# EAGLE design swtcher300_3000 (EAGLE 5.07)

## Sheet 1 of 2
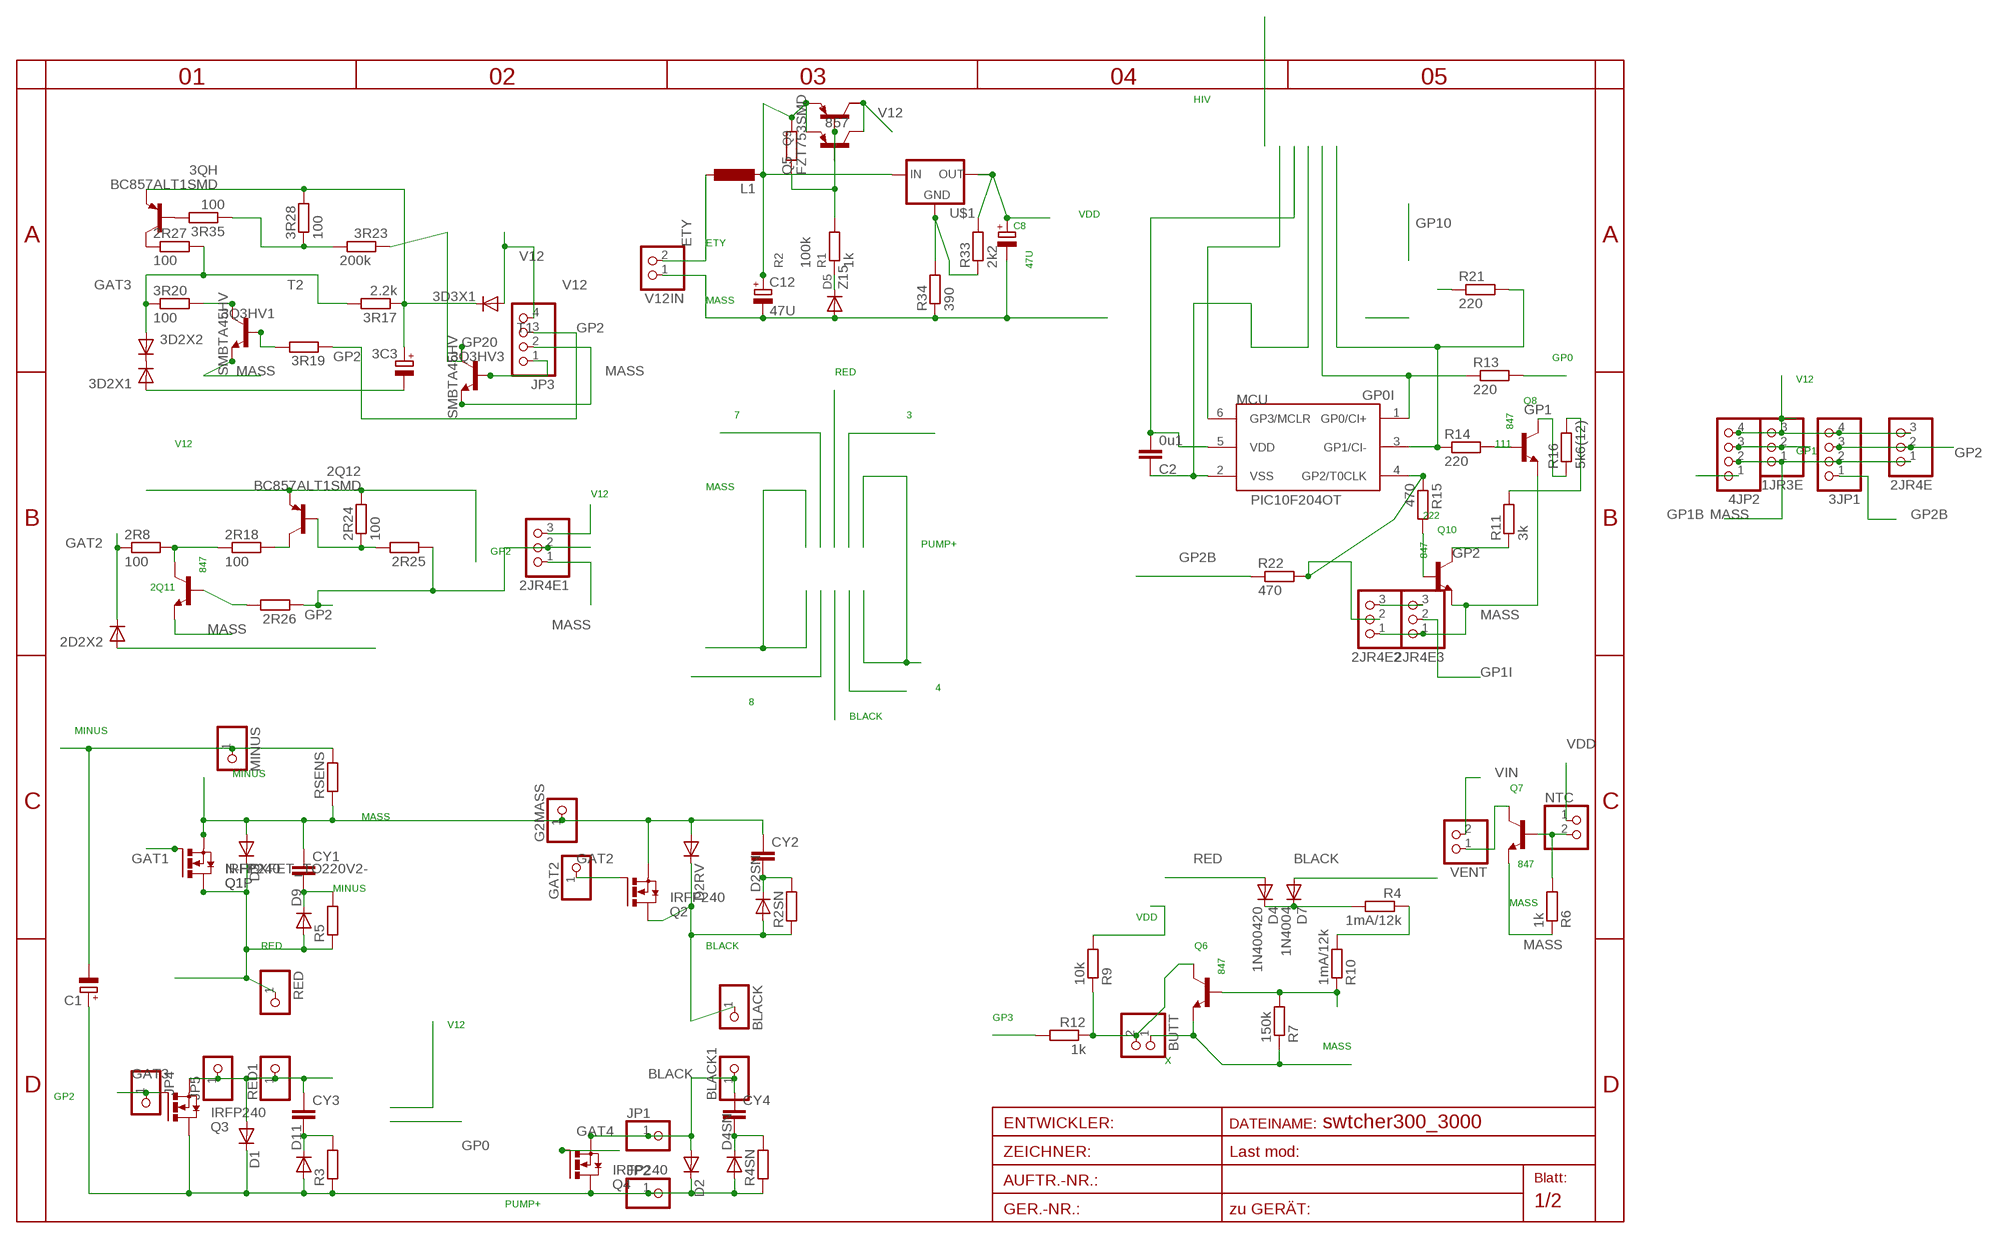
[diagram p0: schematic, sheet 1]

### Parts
1JR3E  PINHD-1X3  [1X03]
2D2X2  DIODE-MINIMELF  [MINIMELF]
2JR4E  PINHD-1X3  [1X03]
2JR4E1  PINHD-1X3  [1X03]
2JR4E2  PINHD-1X3  [1X03]
2JR4E3  PINHD-1X3  [1X03]
2Q11  847  BC847ALT1SMD  [SOT23]
2Q12  BC857ALT1SMD  [SOT23-BEC]
2R8  100  R-EU_R0805  [R0805]
2R18  100  R-EU_R0805  [R0805]
2R24  100  R-EU_R0805  [R0805]
2R25  R-EU_R0805  [R0805]
2R26  R-EU_R1206  [R1206]
2R27  100  R-EU_0207/10  [0207/10]
3C3  CPOL-EUD  [PANASONIC_D]
3D2X1  DIODE-MINIMELF  [MINIMELF]
3D2X2  DIODE-MINIMELF  [MINIMELF]
3D3X1  DIODE-SMA-DO214  [SMA-DO214AC]
3JP1  PINHD-1X4  [1X04]
3Q3HV1  SMBTA45HV  [SOT23HV]
3Q3HV3  SMBTA45HV  [SOT23HV]
3QH  BC857ALT1SMD  [SOT23-BEC]
3R17  2.2k  R-EU_R1206  [R1206]
3R19  R-EU_0204/3  [0204/3]
3R20  100  R-EU_0207/12  [0207/12]
3R23  200k  R-EU_0204/3  [0204/3]
3R28  100  R-EU_R0805  [R0805]
3R35  100  R-EU_R0805  [R0805]
4JP2  PINHD-1X4  [1X04]
BLACK  PINHD-1X14.5MM  [1X4MM5]
BLACK1  PINHD-1X12MM3  [1X2MM3]
BUTT  PINHD-1X2STR  [1X02]
C1  CPOL-EUE5-13  [E5-13]
C2  0u1  C-EUC0805  [C0805]
C8  47U  CPOL-EUD  [PANASONIC_D]
C12  47U  CPOL-EUSMCA  [SMC_A]
CY1  CXXC10B6  [XC10B6]
CY2  CXXC10B6  [XC10B6]
CY3  CXXC22B7  [XC22B7]
CY4  CXXC10B5  [XC10B5]
D1  DIODE-SMC  [SMC]
D2  DIODE-SMC  [SMC]
D2RV  DIODE-SMC  [SMC]
D2SN  DIODE-SOD61E  [SOD61E]
D3  DIODE-SMC  [SMC]
D4  1N400420  [DO41-20]
D4SN  DIODE-P1-10  [P1-10]
D5  Z15  DIODE-MINIMELF  [MINIMELF]
D7  1N4004  [D-7.5]
D9  DIODE-SOD61E  [SOD61E]
D11  DIODE-D-12.5  [D-12.5]
G2MASS  PINHD-1X11MM0  [1X1MM0]
GAT2  PINHD-1X11MM0  [1X1MM0]
JP1  PINHD-1X11MM0  [1X1MM0]
JP2  PINHD-1X11MM0  [1X1MM0]
JP3  PINHD-1X4  [1X04]
JP4  PINHD-1X11MM0  [1X1MM0]
JP5  PINHD-1X11MM0  [1X1MM0]
L1  L-EU0204/5  [0204/5]
MCU  PIC10F204OT  [SOT23-6]
MINUS  PINHD-1X14.5MM  [1X4MM5]
NTC  PINHD-1X2STR  [1X02]
Q1  IRFP240  [TO247BV]
Q1P  N-HEXFET_TO220V2-  [TO220BV2]
Q2  IRFP240  [TO247BV]
Q3  IRFP240  [TO247BV]
Q4  IRFP240  [TO247BV]
Q5  FZT753SMD  [SOT223]
Q6  847  BC847ALT1SMD  [SOT23]
Q7  847  BC847ALT1SMD  [SOT23]
Q8  847  BC847ALT1SMD  [SOT23]
Q9  857  BC857ALT1SMD  [SOT23-BEC]
Q10  847  BC847ALT1SMD  [SOT23]
R1  1k  R-EU_R0805  [R0805]
R2  100k  R-EU_R0805  [R0805]
R2SN  R-EU_0617/22  [0617/22]
R3  R-EU_0617/17  [0617/17]
R4  1mA/12k  R-EU_R1210  [R1210]
R4SN  R-EU_0207/10  [0207/10]
R5  R-EU_0617/22  [0617/22]
R6  1k  R-EU_R0805  [R0805]
R7  150k  R-EU_R0805  [R0805]
R9  10k  R-EU_R0805  [R0805]
R10  1mA/12k  R-EU_R1210  [R1210]
R11  3k  R-EU_R1206  [R1206]
R12  1k  R-EU_R0805  [R0805]
R13  220  R-EU_R0805  [R0805]
R14  220  R-EU_R0805  [R0805]
R15  470  R-EU_R0805  [R0805]
R16  5k6(12)  R-EU_R0805  [R0805]
R21  220  R-EU_R0805  [R0805]
R22  470  R-EU_R1206  [R1206]
R33  2k2  R-EU_R0805  [R0805]
R34  390  R-EU_R0805  [R0805]
RED  PINHD-1X14.5MM  [1X4MM5]
RED1  PINHD-1X12MM3  [1X2MM3]
RSENS  R-EU_CERAM35  [CERAM35]
T1  2N2222-NPN-TO92-EBC  [TO92-EBC]
T2  2N2222-NPN-TO92-EBC  [TO92-EBC]
U$1  AP1117  [SOT223]
V12IN  PINHD-1X2STR  [1X02]
VENT  PINHD-1X2STR  [1X02]

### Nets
111: Q8.1(B) R14.2
222: Q10.1(B) R15.2
BLACK: BLACK1.1 BLACK.1 CY4.1 D2.A D2RV.C D2SN.A D7.A JP1.1 Q2.D Q4.S R2SN.1
BTRAP+: 3C3.+ 3D3X1.K(C) 3QH.E 3R17.1 3R28.2
ETY: L1.1 V12IN.2
GAT1: Q1.G Q1P.G
GAT2: 2D2X2.C 2R8.1 GAT2.1 Q2.G
GAT3: 2R27.2 3D2X2.A 3R17.2 3R20.1 JP4.1 Q3.G
GAT4: Q4.G
GP0: R13.2
GP0I: MCU.1(GP0/CI+) R13.1 ; also sheet 2
GP1: 1JR3E.2 4JP2.3 Q8.3(C) R16.1
GP1B: 4JP2.1 R21.1
GP1I: 2JR4E3.2 MCU.3(GP1/CI-) R14.1 R21.2 ; also sheet 2
GP2: 2JR4E1.2 2JR4E.2 2R25.1 2R26.1 3JP1.3 3R19.1 JP3.3 Q10.3(C) R11.1
GP2B: 3JP1.1 3Q3HV3.1(B) JP3.1 R22.1 T1.B
GP2I: 2JR4E2.2 MCU.4(GP2/T0CLK) R15.1 R22.2 ; also sheet 2
GP3: MCU.6(GP3/MCLR) R12.2 ; also sheet 2
GP20: 3Q3HV3.3(C) 3R23.2 T1.C
HVC1: 3Q3HV1.3(C) 3R20.2 T2.C
MASS: 1JR3E.1 2D2X2.A 2JR4E1.1 2JR4E2.1 2JR4E3.1 2JR4E.1 2Q11.2(E) 3JP1.2 3Q3HV1.2(E) 3Q3HV3.2(E) 4JP2.2 BUTT.1 C2.1 C8.- C12.- CY1.1 CY2.1 D2RV.A D3.A D5.A G2MASS.1 JP3.2 MCU.2(VSS) Q1.S Q1P.S Q2.S Q6.2(E) Q7.2(E) Q8.2(E) Q10.2(E) R6.1 R7.1 R34.1 RSENS.1 T1.E T2.E V12IN.1 ; also sheet 2
MINUS: C1.- MINUS.1 RSENS.2
N$1: D4.C D7.C R4.2
N$2: Q5.1(B) Q9.B R1.2 R2.1
N$3: D5.C R1.1
N$4: 2Q11.3(C) 2R8.2 2R18.1
N$5: Q6.1(B) R7.2 R10.1
N$6: 2Q12.B 2R24.1 2R25.2
N$7: R4.1 R10.2
N$8: 2Q12.C 2R18.2
N$9: NTC.2 Q7.1(B) R6.2
N$10: Q7.3(C) VENT.1
N$12: 3Q3HV1.1(B) 3R19.2 T2.B
N$13: 2R27.1 3QH.C
N$17: 3QH.B 3R35.2
N$18: 3R23.1 3R28.1 3R35.1
N$21: 3D2X1.C 3D2X2.C
N$22: 2Q11.1(B) 2R26.2
N$30: R33.1 R34.2 U$1.1(GND)
PUMP+: C1.+ D1.C D2.C D4SN.A D11.A JP2.1 Q3.D Q4.D R3.1 R4SN.1 ; also sheet 2
RED: 3C3.- 3D2X1.A CY3.1 D1.A D3.C D4.A D9.A JP5.1 Q1.D Q1P.D Q3.S R5.1 RED1.1 RED.1
SNUB1: CY3.2 D11.C R3.2
SNUB2: CY4.2 D4SN.C R4SN.2
SNUB3: CY2.2 D2SN.C R2SN.2
SNUB4: CY1.2 D9.C R5.2
V12: 1JR3E.3 2JR4E1.3 2JR4E2.3 2JR4E3.3 2JR4E.3 2Q12.E 2R24.2 3D3X1.A 3JP1.4 4JP2.4 JP3.4 Q5.2(C) Q9.C R11.2 R16.2
VDD: C2.2 C8.+ MCU.5(VDD) NTC.1 R9.2 R33.2 U$1.2(OUT) U$1.4(TAB) ; also sheet 2
VIN: C12.+ L1.2 Q5.3(E) Q9.E R2.2 U$1.3(IN) VENT.2
X: BUTT.2 Q6.3(C) R9.1 R12.1
Unconnected: Q5.4(C/)

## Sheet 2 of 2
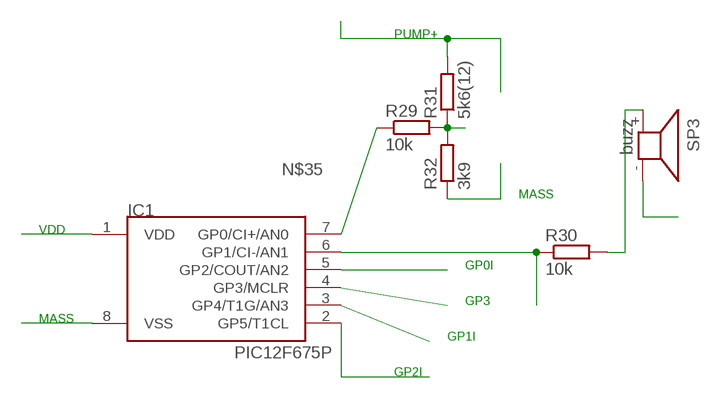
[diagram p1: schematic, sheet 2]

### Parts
IC1  PIC12F675P  [DIL8]
R29  10k  R-EU_R0805  [R0805]
R30  10k  R-EU_R0805  [R0805]
R31  5k6(12)  R-EU_0207/30  [0207/30]
R32  3k9  R-EU_R0805  [R0805]
SP3  buzz  KSS12017MM  [KSS1202]

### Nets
GP0I: IC1.5(GP2/COUT/AN2) ; also sheet 1
GP1I: IC1.3(GP4/T1G/AN3) ; also sheet 1
GP2I: IC1.2(GP5/T1CL) ; also sheet 1
GP3: IC1.4(GP3/MCLR) ; also sheet 1
MASS: IC1.8(VSS) R32.1 SP3.- ; also sheet 1
N$24: R30.2 SP3.+
N$31: IC1.6(GP1/CI-/AN1) R30.1
N$34: R29.2 R31.1 R32.2
N$35: IC1.7(GP0/CI+/AN0) R29.1
PUMP+: R31.2 ; also sheet 1
VDD: IC1.1(VDD) ; also sheet 1

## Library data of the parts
1JR3E 2JR4E 2JR4E1-2JR4E3 = pinhead:PINHD-1X3: PIN HEADER
2D2X2 3D2X1 3D2X2 3D3X1 D1 D2 D2RV D2SN D3 D4SN D5 D9 D11 = diode:DIODE-: DIODE
2Q11 Q6-Q8 Q10 = transistor-npn:BC847*: NPN Transistor
2Q12 3QH Q9 = transistor-pnp:BC857*: PNP Transistror
2R8 2R18 2R24-2R27 3R17 3R19 3R20 3R23 3R28 3R35 R2SN R4 R4SN R5-R7 R9 R10 R12 RSENS = rcl:R-EU_: RESISTOR, European symbol
3C3 C1 = rcl:CPOL-EU: POLARIZED CAPACITOR, European symbol
3JP1 4JP2 JP3 = pinhead:PINHD-1X4: PIN HEADER
3Q3HV1 3Q3HV3 = transistor-npn:SMBTA45
BLACK BLACK1 G2MASS GAT2 JP1 JP2 JP4 JP5 MINUS RED RED1 = pinhead:PINHD-1X1: PIN HEADER
BUTT NTC V12IN VENT = pinhead:PINHD-1X2: PIN HEADER
C2 = rcl:C-EU: CAPACITOR, European symbol
C8 C12 = rcl-2:CPOL-EU: POLARIZED CAPACITOR, European symbol
CY1-CY4 = rcl:CX: X CAPACITOR
D4 D7 = diode:1N4004: DIODE
IC1 = microchip-5:PIC12F6*: uPC nW 1k Program Flash memory 2x Timer Comparator 10b A/D converter/ 4xIN
L1 = rcl:L-EU: INDUCTOR, European symbol
MCU = microchip-3:PIC10F2*: uPC nW 0,25/0,5k Program Flash memory Comparator
Q1-Q4 = transistor-power:IRFP240: HEXFET Power MosFet Source: http://www.irf.com/
Q1P = transistor-power:N-HEXFET_?-*: HEXFET® Power MOSFET
Q5 = transistor-pnp:FZT753SMD: PNP Transistor
R1-R3 R11 R13-R16 R21 R22 R29-R34 = rcl-2:R-EU_: RESISTOR, European symbol
SP3 = buzzer:KSS1201: SPEAKER
T1 T2 = transistor-neu-to92:*-NPN-: NPN Transistror
U$1 = v-reg:AP1117

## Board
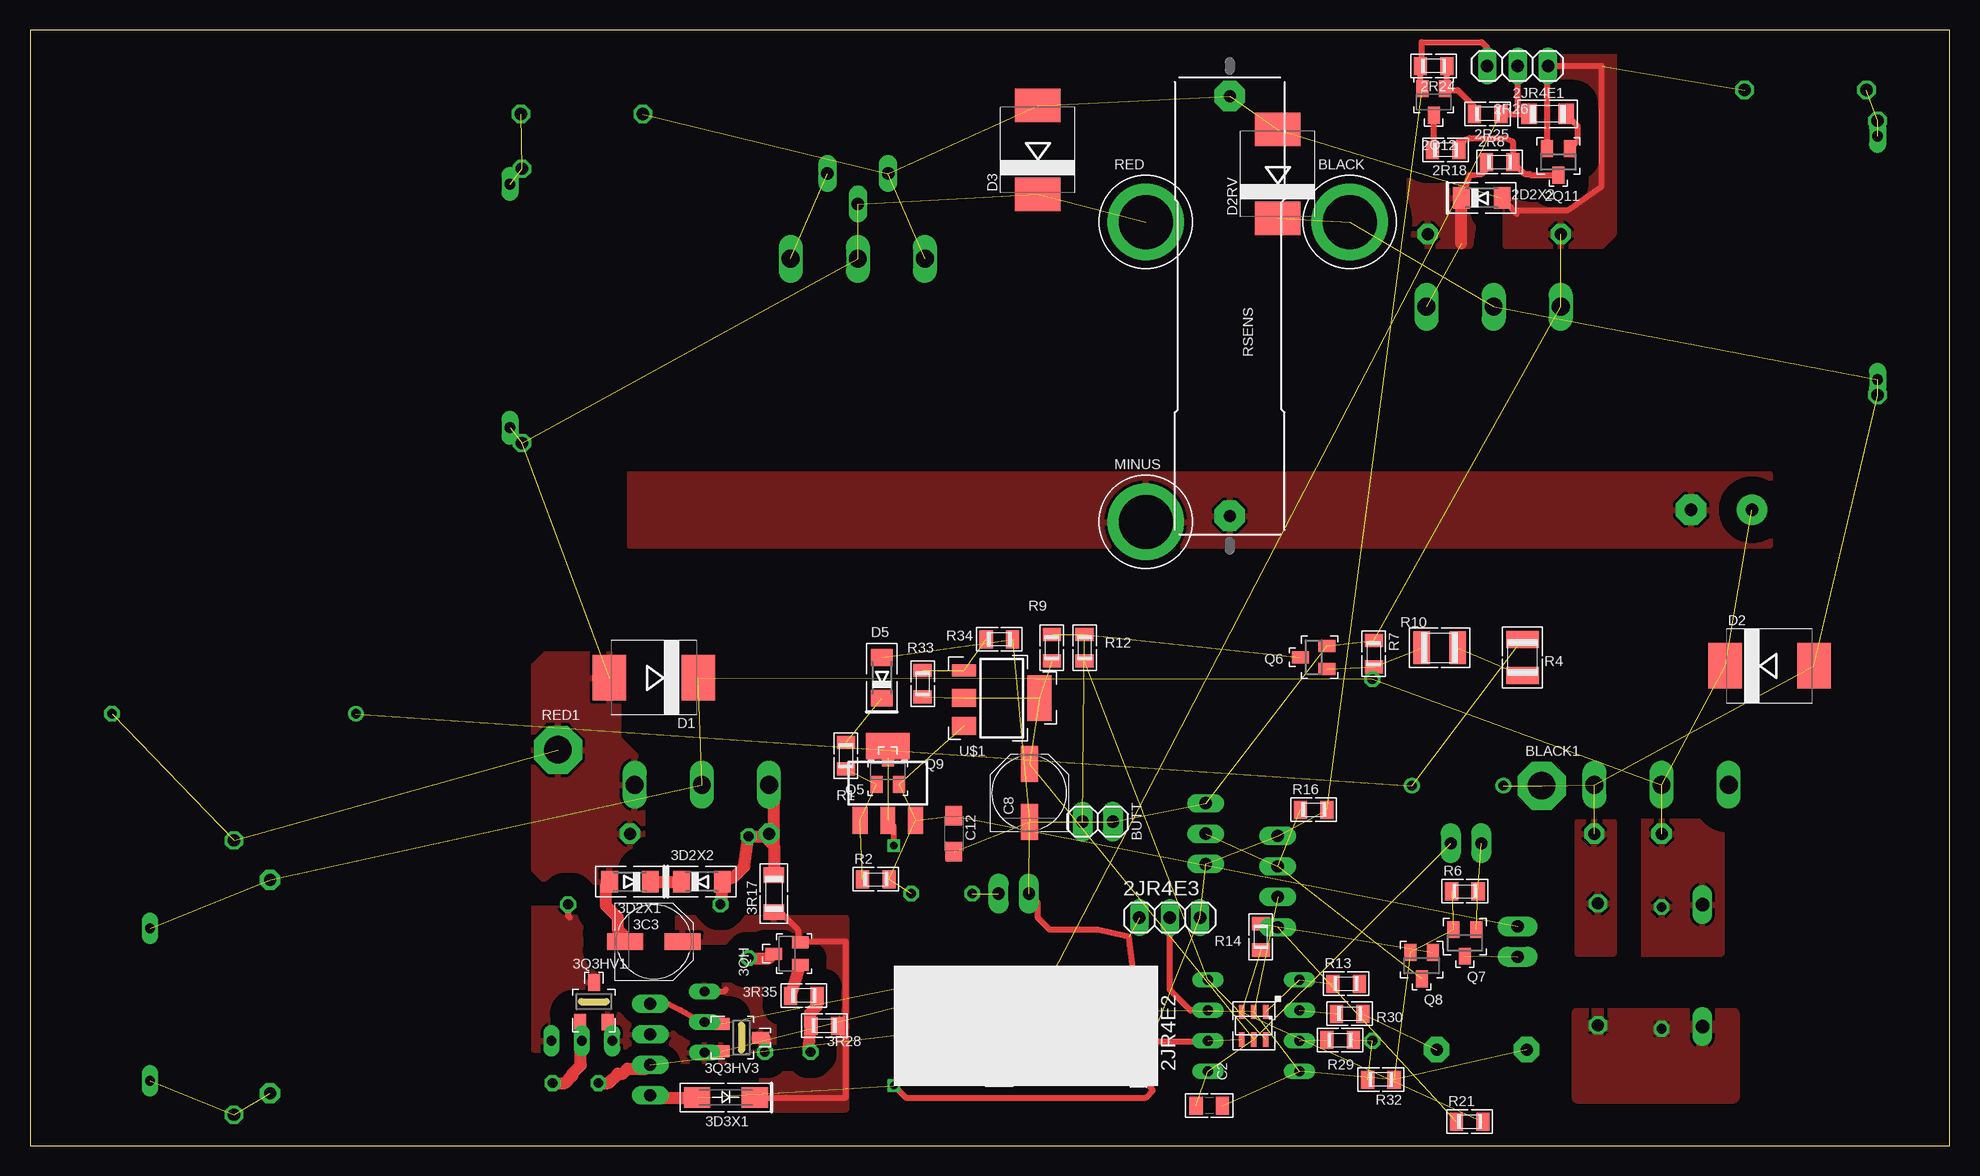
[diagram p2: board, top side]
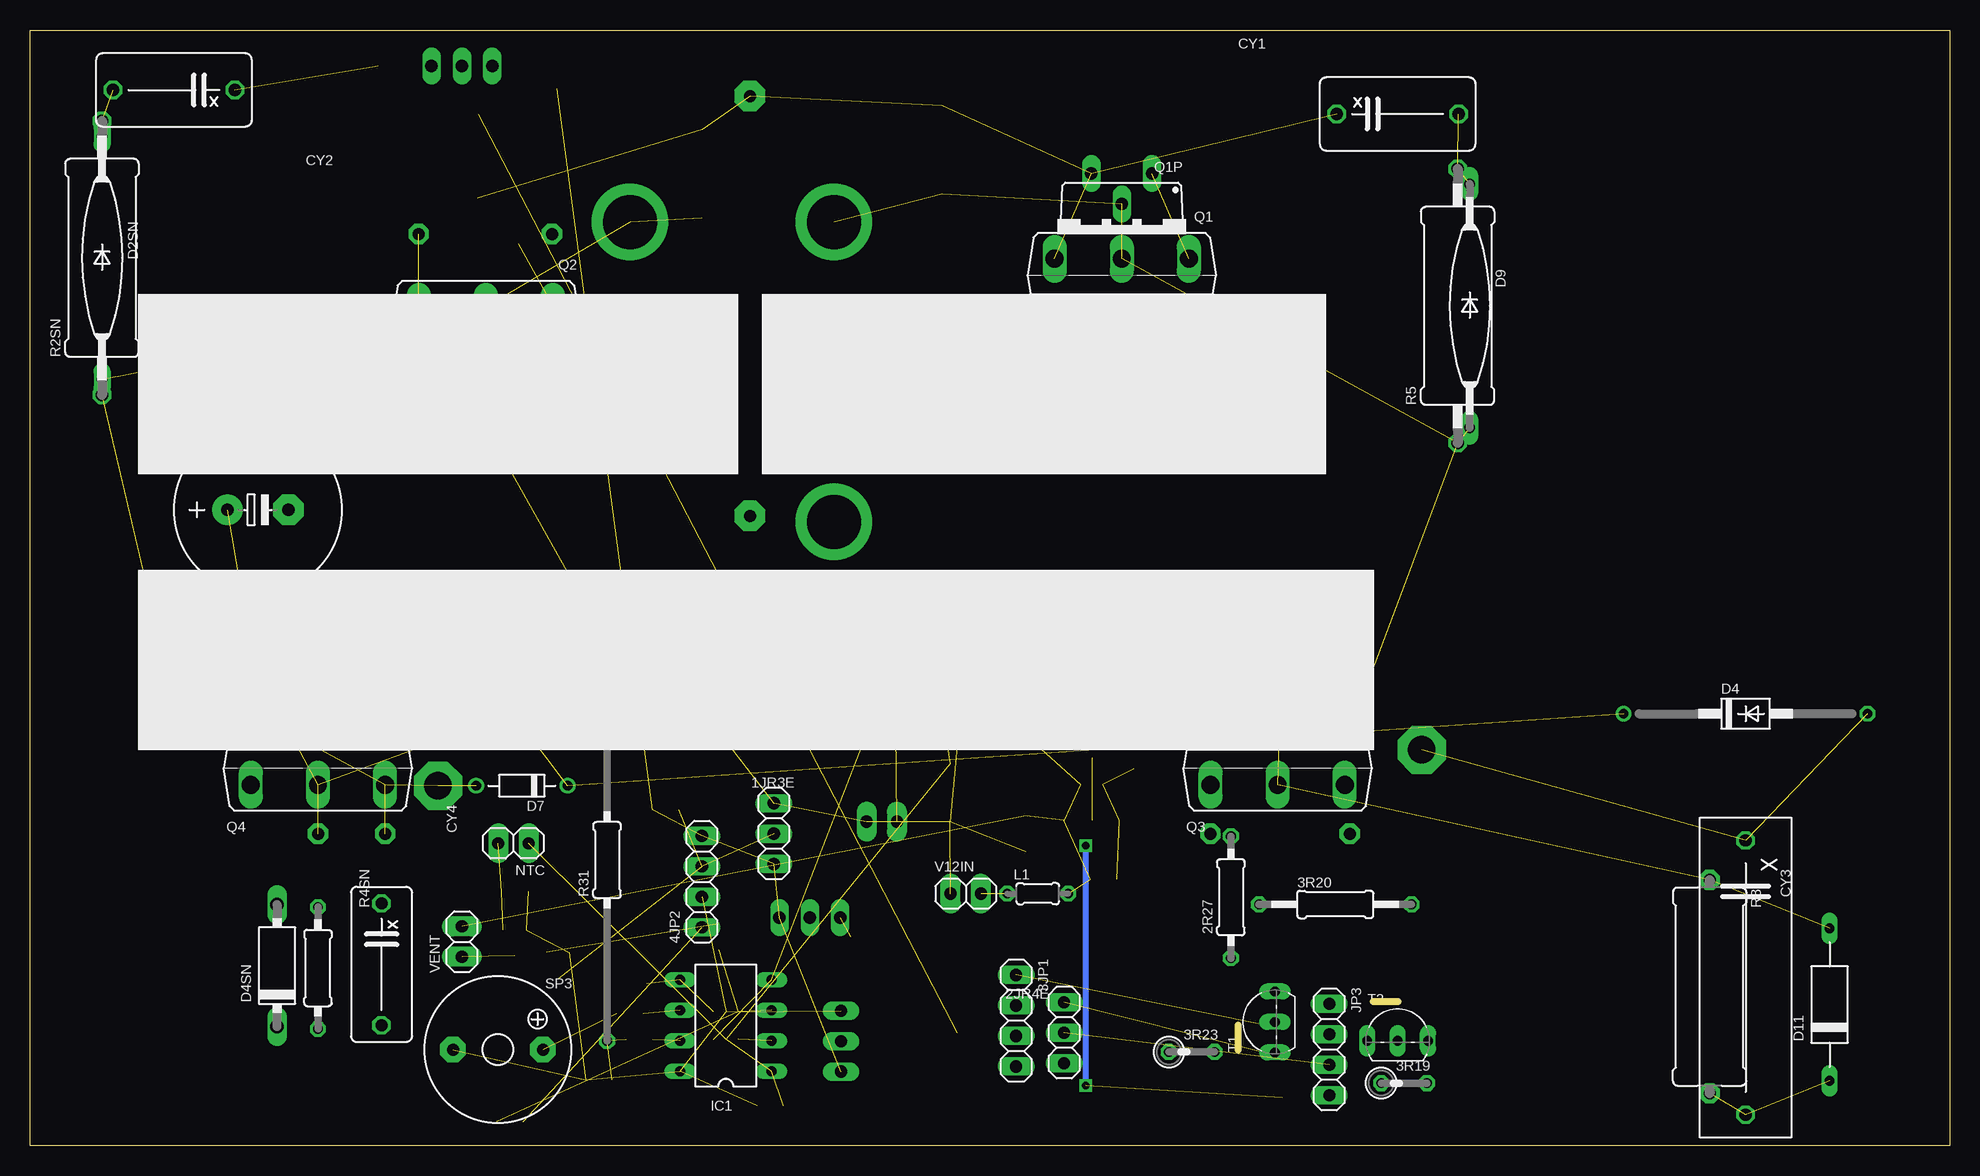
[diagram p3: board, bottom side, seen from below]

Size 160 x 93 mm. Coordinates in mm from the lower left corner, seen from the top.
Outline: 0,0 160,0 160,93 0,93 0,0
Copper layers (1*16): Top 0.035mm / dielectric 1.5mm / Bottom 0.035mm
Design rules "default *": minimum track width 10mil, minimum drill 20mil, track to track 8mil, track to pad 8mil, pad to pad 8mil, via to via 8mil, smd to smd 8mil, copper to edge 40mil, drill to drill 8mil, minimum pad ring 10mil, minimum via ring 8mil, stop-mask expansion 4mil, vias tented up to drill 0mil, thermal gap 10mil

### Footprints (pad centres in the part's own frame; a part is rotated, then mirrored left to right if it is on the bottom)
1X03 = drill 1.016 long: 1 -2.54,0; 2 0,0; 3 2.54,0
MINIMELF = smd 1.4 x 1.8: A 1.7,0; C -1.7,0
SOT23 = smd 1 x 1.4: 1 -0.95,-1.1; 2 0.95,-1.1; 3 0,1.1
SOT23-BEC = smd 1 x 1.4: B -0.95,-1.1; C 0,1.1; E 0.95,-1.1
R0805 = smd 1.1 x 1.5: 1 -1.1,0; 2 1.1,0
R1206 = smd 1.3 x 1.7: 1 -1.55,0; 2 1.55,0
0207/10 = drill 0.813 octagon: 1 -5.08,0; 2 5.08,0
PANASONIC_D = smd 3 x 1.4: + 2.4,0; - -2.4,0
SMA-DO214AC = smd 2.2 x 1.7: A 2.4,0; K -2.4,0
1X04 = drill 1.016 long: 1 -3.81,0; 2 -1.27,0; 3 1.27,0; 4 3.81,0
SOT23HV = smd 1 x 1.4: 1 -1.15,-1.7; 2 1.15,-1.7; 3 0,1.6
0204/3 = drill 0.813 octagon: 1 -1.27,0; 2 2.54,0
0207/12 = drill 0.813 octagon: 1 -6.35,0; 2 6.35,0
1X4MM5 = drill 4.5 pad 6.35 round: 1 0,0
1X2MM3 = drill 2.3 pad 4 octagon: 1 0,0
1X02 = drill 1.016 pad 1.676 long: 1 -1.27,0; 2 1.27,0
E5-13 = drill 1.016 pad 2.54 round: + -2.54,0 | drill 1.016 pad 2.54 octagon: - 2.54,0
C0805 = smd 1.1 x 1.5: 1 -1.1,0; 2 1.1,0
SMC_A = smd 1.6 x 1.4: + -1.5,0; - 1.5,0
XC10B6 = drill 1.016 octagon: 1 -5.08,0; 2 5.08,0
XC22B7 = drill 1.016 octagon: 1 -11.43,0; 2 11.43,0
XC10B5 = drill 1.016 octagon: 1 -5.08,0; 2 5.08,0
SMC = smd 2.8 x 3.8: A 3.7,0; C -3.7,0
SOD61E = drill 0.914 long: A 10.16,0; C -10.16,0
DO41-20 = drill 0.8 octagon: A 10.16,0 | drill 0.8 round: C -10.16,0
P1-10 = drill 1.118 long: A 5.08,0; C -5.08,0
D-7.5 = drill 0.8 round: A 3.81,0; C -3.81,0
D-12.5 = drill 0.813 long: A 6.35,0; C -6.35,0
1X1MM0 = drill 1 pad 1.676 octagon: 1 0,0
DIL8 = drill 0.8 long: 1 -3.81,-3.81; 2 -1.27,-3.81; 3 1.27,-3.81; 4 3.81,-3.81; 5 3.81,3.81; 6 1.27,3.81; 7 -1.27,3.81; 8 -3.81,3.81
0204/5 = drill 0.813 octagon: 1 -2.54,0; 2 2.54,0
SOT23-6 = smd 0.45 x 1.2: 1 -1.016,-1.15; 2 0,-1.15; 3 1.016,-1.15; 4 1.016,1.15; 5 0,1.15; 6 -1.016,1.15
TO247BV = drill 1.499 long: D 0,-2.921; G -5.588,-2.921; S 5.588,-2.921
TO220BV2 = drill 1.016 long: D 0,0; G -2.54,-2.54; S 2.54,-2.54
SOT223 = smd 1.219 x 2.235: 1 -2.311,-3.099; 2 0,-3.099; 3 2.311,-3.099 | smd 3.6 x 2.2: 4 0,3.099
0617/22 = drill 1.016 octagon: 1 -11.43,0; 2 11.43,0
0617/17 = drill 1 pad 1.676 octagon: 1 -8.89,0; 2 8.89,0
R1210 = smd 1.4 x 2.7: 1 -1.5,0; 2 1.5,0
0207/30 = drill 0.813 octagon: 1 -15.08,0; 2 15.08,0
CERAM35 = drill 1 pad 2.54 octagon: 1 -17.5,0; 2 17.5,0
KSS1202 = drill 1 pad 2.159 octagon: + 3.75,0; - -3.75,0
TO92-EBC = drill 0.813 long: B 0,-1.27; C 2.54,-1.27; E -2.54,-1.27
SOT223' = smd 1 x 2: 1 -2.3,-3.15 | smd 1.5 x 2: 2 0,-3.15; 3 2.3,-3.15 | smd 3.8 x 2: 4 0,3.15

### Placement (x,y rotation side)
1JR3E  98,26 270 bottom
2D2X2  121,79 0 top
2JR4E  73.8,9.4 270 bottom
2JR4E1  124,90 180 top
2JR4E2  92.4,8.7 270 top
2JR4E3  95,19 0 top
2Q11  127.4,82 180 top
2Q12  117,87 180 top
2R8  122.5,82 0 top
2R18  118,83 180 top
2R24  117,90 180 top
2R25  121.5,86 180 top
2R26  126.5,86 0 top
2R27  59.9,20.7 90 bottom
3C3  52,17 0 top
3D2X1  50,22 180 top
3D2X2  56,22 0 top
3D3X1  58,4 180 top
3JP1  77.8,10.4 270 bottom
3Q3HV1  47,12 0 top
3Q3HV3  59.3,9 270 top
3QH  63.1,16 90 top
3R17  62,21 90 top
3R19  46.1,5.2 0 bottom
3R20  51.2,20.1 0 bottom
3R23  63.8,7.8 0 bottom
3R28  66.2,10 0 top
3R35  64.5,12.5 180 top
4JP2  104,22 90 bottom
BLACK  110,77 0 top
BLACK1  126,30 0 top
BUTT  89,27 180 top
C1  141,53 0 bottom
C2  98.3,3.32 180 top
C8  83.3,29.4 90 top
C12  77,26 270 top
CY1  46,86 0 bottom
CY2  148,88 180 bottom
CY3  17,14 270 bottom
CY4  130.7,15.1 270 bottom
D1  52,39 180 top
D2  145,40 0 top
D2RV  104,81 90 top
D2SN  154,74 270 bottom
D3  84,83 90 top
D4  17,36 0 bottom
D4SN  139.4,15 90 bottom
D5  71,39 90 top
D7  119,30 180 bottom
D9  40,70 270 bottom
D11  10,11.75 90 bottom
G2MASS  127.6,76 0 top
GAT2  116.5,76 0 top
IC1  102,10 90 bottom
JP1  130.4,26 0 top
JP2  136,26 0 top
JP3  51.7,8 270 bottom
JP4  61.6,26 0 top
JP5  50,26 0 top
L1  76,21 0 bottom
MCU  102,10 180 top
MINUS  93,52 0 top
NTC  119.7,25.2 180 bottom
Q1  69,71 180 bottom
Q1P  69,78.5 180 bottom
Q2  122,67 180 bottom
Q3  56,33 0 bottom
Q4  136,33 0 bottom
Q5  71.5,30.2 0 top
Q6  107,40.7 90 top
Q7  119.6,16.9 180 top
Q8  116,15 180 top
Q9  71.5,31.2 0 top
Q10  83.8,9.4 90 top
R1  68,32.5 270 top
R2  70.5,22.2 0 top
R2SN  154,74 90 bottom
R3  20,13.25 270 bottom
R4  124.4,40.7 90 top
R4SN  136,14.8 270 bottom
R5  41,70 90 bottom
R6  119.6,21.2 0 top
R7  112,41 270 top
R9  85.17,41.5 270 top
R10  117.5,41.5 0 top
R11  80.8,7.4 270 top
R12  87.9,41.5 270 top
R13  109.7,13.5 0 top
R14  102.6,17.4 90 top
R15  88.7,8.2 180 top
R16  107,28 0 top
R21  120,2 0 top
R22  87.8,12.4 270 top
R29  109.2,8.8 0 top
R30  110,11 0 top
R31  111.9,23.8 90 bottom
R32  112.6,5.5 180 top
R33  74.4,38.5 270 top
R34  80.8,42.2 180 top
RED  93,77 0 top
RED1  44,33 0 top
RSENS  100,70 270 top
SP3  121,8 0 bottom
T1  57.5,10.3 90 bottom
T2  46,10 0 bottom
U$1  AP1117  [SOT223']  81,37.3 270 top
V12IN  82,21 0 bottom
VENT  124,17 90 bottom

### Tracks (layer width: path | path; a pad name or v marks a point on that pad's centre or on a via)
111  (1 unrouted)
222
  Top 0.5: R15.2 85.15,8.2 Q10.1
BLACK  (9 unrouted)
  pour Top (isolate 2): 129,27 132,27 132,16 129,16
BTRAP+
  Top 0.5: 3R28.2 67.3,9.7 68,9 | 68,9 68,17 64.25,17 3QH.E | 3R17.1 62.55,19.45 64,18 64,17 | 3D3X1.K 61,4 63,4 68,4 68,9
  pour Top (isolate 1.5): 54,19 68,19 68,17 68,3 61,3 61,6 66,6 66,17 54,17
ETY  (1 unrouted)
GAT1  (1 unrouted)
GAT2  (1 unrouted)
  Top 0.5: 2R8.1 121.7,81.7 121,81 120,80.9 2D2X2.C
  Top 1: 119.3,75.2 2D2X2.C
  pour Top (isolate 2): 115,81 119,81 121,82 120,75 116,75 115,76
GAT3
  Top 0.5: 61.22,25.78 61,26 JP4.1
  Top 1: 3R20.1 57.7,20.25 3D2X2.A 58.7,22.4 59.54,23.24 2R27.2 61.22,25.78 62,25 | 62,25 3R17.2 | 62,25 62,29.67 Q3.G
GP0I  (2 unrouted)
GP1  (3 unrouted)
GP1B  (1 unrouted)
GP1I  (3 unrouted)
  Top 0.5: 2JR4E3.2 95,13 96.73,11.27 IC1.3
GP2  (2 unrouted)
  Top 0.5: 2R25.1 124,86 | 124,86 2R26.1 | 124,86 2JR4E1.2 | 2JR4E.2 77.53,9.4 3JP1.3 80.62,9.13 R11.1 82.25,8.95 Q10.3
  Top 1: 3R19.1 48.2,5.2 49,6 49.4,6 49.8,6.4 51.37,6.4 JP3.3
GP2B  (1 unrouted)
  Top 0.5: R22.1 78.54,13.95 3JP1.1 | JP3.1 53.19,11.81 54.2,11.3 55.43,10.6 T1.B 56.38,10.15 3Q3HV3.1
GP2I  (1 unrouted)
  Top 0.5: R22.2 88.35,10.85 89.8,9.4 R15.1 91.9,8.2 2JR4E2.2 98.16,8.7 IC1.2
GP3  (2 unrouted)
GP20
  Top 0.5: T1.C 57.84,12.84 58,13
  Top 1: 3R23.2 61.26,8.94 3Q3HV3.3
  pour Top (isolate 1.8, rank 2): 55.1,13.4 61.1,13.4 62,13 62,8 60,8 60,11 59,12 55,12
HVC1
  Top 0.5: 3R20.2 44.85,19.15 45,19
  pour Top (isolate 2, rank 2): 46,21 42,21 42,8 44,8 44,11 45,12 46,12 47,13 47,19 46,20
MASS  (28 unrouted)
  Top 0.5: 3Q3HV3.2 56.32,7.85 T1.E | 3Q3HV1.2 48.15,9.12 T2.E | 123.33,78.3 123.9,77.68 | 123.33,78.3 2D2X2.A | 2Q11.2 126.45,89.91 2JR4E1.1 131,90 131,80 128.2,78 123.64,78 123.33,78.3 | 84.8,11.4 84.8,10.45 Q10.2 | 84.8,11.4 84.8,12.4 90.8,12.4 92.4,11.8 2JR4E2.1 91.6,17.4 89,18 85,18 84,19 84,20.27 V12IN.1 | 84.8,11.4 84.53,11.67 3JP1.2 77.53,11.94 2JR4E.1
  pour Top (isolate 1, rank 2): 48,11 49,11 50,10 53,10 54,9 57,9 58,8 58,7 54,7 53,8 48,8
  pour Top (isolate 2): 126,92 131,92 132,91 132,76 131,75 123,75 123,79 125,81 125,82 126,83 126,91
MINUS
  pour Top (isolate 1.5, rank 5): 145,50 50,50 50,56 145,56
N$1  (2 unrouted)
N$2  (3 unrouted)
N$3  (1 unrouted)
N$4
  Top 0.5: 2R18.1 119.1,83.7 120,84 123,84 123.6,83.7 2R8.2 124.6,81 125,81 125.1,80.9 2Q11.3
N$5  (2 unrouted)
N$6
  Top 0.5: 2R25.2 120.5,86.5 119,88 118.05,88 2Q12.B 118.1,88.25 2R24.1
N$7  (1 unrouted)
N$8
  Top 0.5: 2Q12.C 117,83.1 2R18.2
N$9  (2 unrouted)
N$10  (1 unrouted)
N$12
  Top 0.5: 3Q3HV1.1 45.85,8.88 T2.B
  Top 1: 3R19.2 44.6,5.2 45.2,5.8 45.2,6 45.9,6.7 45.9,8.63 T2.B
N$13
  Top 1: 2R27.1 61.62,15.62 3QH.C
N$17
  Top 1: 3R35.2 3QH.B
N$18
  Top 1: 3R35.1 65.6,11.6 65,11 65,10.1 3R28.1 64.9,7.97 3R23.1
N$21
  Top 1: 3D2X1.C 3D2X2.C
N$22
  Top 0.5: 2R26.2 128.05,85.95 129,85 129,83.75 2Q11.1
N$24  (1 unrouted)
N$30  (2 unrouted)
N$31  (1 unrouted)
N$34  (2 unrouted)
N$35  (1 unrouted)
PUMP+  (8 unrouted)
  pour Top (isolate 2, rank 2): 134,27 134,16 141,16 141,27
RED  (8 unrouted)
  Top 1: 3C3.- 49.95,17.05 49,18 49,19 48,20 48,21.7 3D2X1.A
  pour Top (isolate 2): 43,41 49,41 49,34 51,32 51,23 50,23 49,22 43,22 42,23 42,40
SNUB1  (2 unrouted)
SNUB2
  pour Top (isolate 2, rank 2): 129,11 142,11 142,4 129,4 129,10
SNUB3  (2 unrouted)
SNUB4  (2 unrouted)
V12  (via drill 0.6)  (7 unrouted)
  Top 0.5: 2JR4E1.3 121.46,91.54 121,92 116,92 116,90.1 2R24.2 115.9,88.25 2Q12.E | v72,5 73,4 93,4 93.6,4.6 2JR4E2.3 92.09,5.85 R11.2 80.06,6.59 3JP1.4 77.53,6.86 2JR4E.3 | v72,25 72,26.6 Q5.2
  Top 1: 3D3X1.A 52.19,4 JP3.4
  Bottom 0.5: v72,5 v72,25
VDD  (8 unrouted)
VIN  (6 unrouted)
X  (3 unrouted)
